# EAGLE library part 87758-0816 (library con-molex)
8 Pin - 2mm Dual Row Single Wafer, Vertical T/H HDR Source: http://www.molex.com/pdm_docs/sd/877580616_sd.pdf
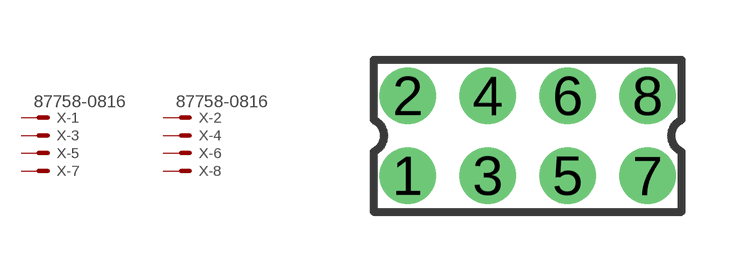
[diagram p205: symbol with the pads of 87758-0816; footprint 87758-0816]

Designator prefix X; gates -1=MV -2=MV -3=M -4=M -5=M -6=M -7=M -8=M

## 87758-0816 (MF: MOLEX; MPN: 87758-0816; OC_FARNELL: 7472331; OC_NEWARK: 59J1556)  [87758-0816]
1  -1:S  pas
2  -2:S  pas
3  -3:S  pas
4  -4:S  pas
5  -5:S  pas
6  -6:S  pas
7  -7:S  pas
8  -8:S  pas

## Footprint 87758-0816 (pad centres in mm)
8 Pin - 2mm Dual Row Single Wafer, Vertical T/H HDR Source: http://www.molex.com/pdm_docs/sd/877580616_sd.pdf
drill 0.9 pad 1.27 round: 1 -3,-1; 2 -3,1; 3 -1,-1; 4 -1,1; 5 1,-1; 6 1,1; 7 3,-1; 8 3,1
